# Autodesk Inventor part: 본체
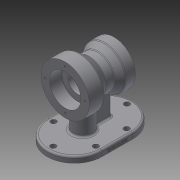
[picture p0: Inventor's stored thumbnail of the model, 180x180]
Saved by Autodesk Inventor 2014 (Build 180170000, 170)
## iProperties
Created: 2020-01
Part Number: 본체
Material: Generic
Document SubType Name: Modeling
Designer: kh
Density: 1 g/cm^3
Appearance: Default
Author: kh
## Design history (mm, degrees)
sketch "Sketch1"
  geometry: L1 (-25, -45)-(25, -45); L2 (25, 45)-(-25, 45); L3 (-25, -45)-(25, 45); L4 (25, -45)-(-25, 45); A1 r 45 centre (25, 0) between (25, -45) and (25, 45); A2 r 45 centre (-25, 0) between (-25, 45) and (-25, -45); 1 further point
  constraints: 8 end point, 4 point on circle, 2 centre point, 2 midpoint, 1 horizontal, 1 parallel
  dimensions: "d1" = 90 distance of L1.end L2.start; "d2" = 90 distance between parallel lines of L1 L2; "d3" = 45 radius of A2
extrude "Extrusion1" new body sketch "Sketch1" distance "d4" = 10; taper "d5" = 0 deg
sketch "Sketch3"
  geometry: L1 (0, 0)-(0, 80); L2 (-40, 80)-(40, 80); L3 (-25, 10)-(-70, 10) reference; L4 (-70, 10)-(-40, 10); L5 (-40, 80)-(-40, 120); L6 (-40, 120)-(-16, 120); L7 (-16, 120)-(-1.103, 107.5); L8 (-1.103, 107.5)-(13.289, 107.5); L9 (13.289, 107.5)-(24, 115); L10 (24, 115)-(40, 115); L11 (40, 115)-(40, 80)
  constraints: 20 end point, 4 perpendicular, 2 parallel, 1 point on line, 1 vertical
  dimensions: "d6" = 80 distance of L1.start L1.end; "d7" = 30 distance of L3.end L4.end; "d8" = 70 distance of L2.start L4.end; "d10" = 24 distance of L5.end L6.end; "d11" = 16 distance of L9.end L10.end; "d12" = 80 diameter of L6 L2; "d14" = 55 diameter of L8 L2; "d15" = 70 diameter of L10 L2; "d16" = 80 distance between parallel lines of L11 L5; "d17" = 40 deg angle of L8 L7; "d18" = 35 deg angle of L8 L9
revolve "Revolution1" sketch "Sketch3" stored, may be unused: angle "d19" = 90 deg
sketch "Sketch5"
  geometry: C1 r 40 at (0, 0) reference; C2 r 26 at (0, 0); 1 further point
  constraints: 1 centre point, 1 coincident
  dimensions: "d23" = 52 diameter of C2
extrude "Extrusion2" cut sketch "Sketch5" distance "d24" = 20; taper "d25" = 0 deg
sketch "Sketch6"
  geometry: C1 r 26 at (0, 0) reference; C2 r 16 at (0, 0); 1 further point
  constraints: 1 centre point, 1 coincident
  dimensions: "d26" = 32 diameter of C2
sketch "Sketch7"
  geometry: C1 r 35 at (0, 0) reference; C2 r 20 at (0, 0); 1 further point
  constraints: 1 centre point, 1 coincident
  dimensions: "d27" = 40 diameter of C2
extrude "Extrusion3" cut sketch "Sketch7" distance "d28" = 17; taper "d29" = 0 deg
extrude "Extrusion4" cut sketch "Sketch6" stored distance "d30" = 17; taper "d31" = 0 deg
sketch "Sketch8"
  geometry: L1 (25, 45)-(-25, 45) reference; L2 (70, 0)-(60, 0); L3 (-70, 0)-(-60, 0); L4 (25, -35)-(-25, -35); L5 (25, 35)-(-25, 35); A1 r 45 centre (25, 0) between (25, -45) and (25, 45) reference; A2 r 45 centre (-25, 0) between (-25, 45) and (-25, -45) reference; A3 r 35 centre (25, 0) between (25, -35) and (25, 35); A4 r 35 centre (-25, 0) between (-25, 35) and (-25, -35); 7 further points
  constraints: 8 coincident, 8 end point, 8 point on circle, 2 centre point, 2 tangent, 1 collinear, 1 parallel
  dimensions: "d32" = 10 distance of L2.start L2.end; "d33" = 10 distance of L3.start L3.end
hole "Hole1" sketch "Sketch8" at (25, -35), (60, 0), (25, 35), (-25, 35), (-60, 0), (-25, -35) diameter "d34" = 9; stored, may be unused: countersink angle "d38" = 90 deg, drill point angle "d40" = 118 deg; dims "d35" = 6, "d36" = 4, "d37" = 2, "d39" = 8
sketch "Sketch9"
  geometry: L1 (12, 0)-(12, -5); L2 (-3.199, -5)-(-25, -5); L3 (-25, 5)-(-3.199, 5); L4 (12, 5)-(12, 0); L5 (-25, -5)-(-30, -5); L6 (-30, -5)-(-30, 5); L7 (-30, 5)-(-25, 5); A1 r 45 centre (-25, 0) between (-25, 45) and (-25, -45) reference; A2 r 16 centre (12, 0) between (-3.199, -5) and (-3.199, 5); 1 further point
  constraints: 14 end point, 2 equal length, 2 perpendicular, 2 point on circle, 1 centre point
  dimensions: "d42" = 32 diameter of A2; "d43" = 37 distance of L1.start A1.centre (derived); "d44" = 5 distance of L1.start L1.end; "d45" = 37 distance of L1.end L2.end; "d46" = 10 distance of L2.end L3.start; "d70" = 5 distance of L2.end L5.end; "d71" = 10 distance of L5.end L6.end
sketch "Sketch11"
  geometry: C1 r 26 at (0, 0) reference; 2 further points
  dimensions: "d47" = 33 distance of C1.centre point (0, 33)
hole "Hole2" sketch "Sketch11" at (0, 33) diameter "d48" = 3.242; stored, may be unused: countersink angle "d52" = 90 deg, drill point angle "d54" = 118 deg; dims "d49" = 9, "d50" = 4, "d51" = 2, "d53" = 11
pattern_circular "Circular Pattern1" dims angle "d56" = 360 deg
sketch "Sketch13"
  geometry: 2 further points
extrude "Extrusion5" join sketch "Sketch9" stored distance "d72" = 17; taper "d73" = 0 deg
fillet "Fillet1" dims "d74" = 3
fillet "Fillet2" dims "d75" = 3
fillet "Fillet3" dims "d76" = 3
fillet "Fillet4" dims "d77" = 0.3
sketch "Sketch15"
  geometry: L1 (50, 0)-(0, 0) reference; L2 (95, 0)-(95, -7) reference; 2 further points
  constraints: 1 other
  dimensions: "d78" = 70 distance from line of point (25, -4) L2; "d79" = 4 distance from line of L1 point (25, -4)
emboss "Emboss1" sketch "Sketch15" dims "d1" = 90, "d2" = 90, "d3" = 45, "d80" = 0.5, "d81" = 0
sketch "Sketch17"
  geometry: C1 r 20 at (0, 0) reference; 2 further points
  dimensions: "d82" = 27.5 distance of C1.centre point (0, 27.5)
hole "Hole4" sketch "Sketch17" at (0, 27.5) diameter "d83" = 3.242; stored, may be unused: countersink angle "d87" = 90 deg, drill point angle "d89" = 118 deg; dims "d84" = 9, "d85" = 4, "d86" = 2, "d88" = 11
pattern_circular "Circular Pattern3" dims angle "d91" = 360 deg
body "Solid1"
